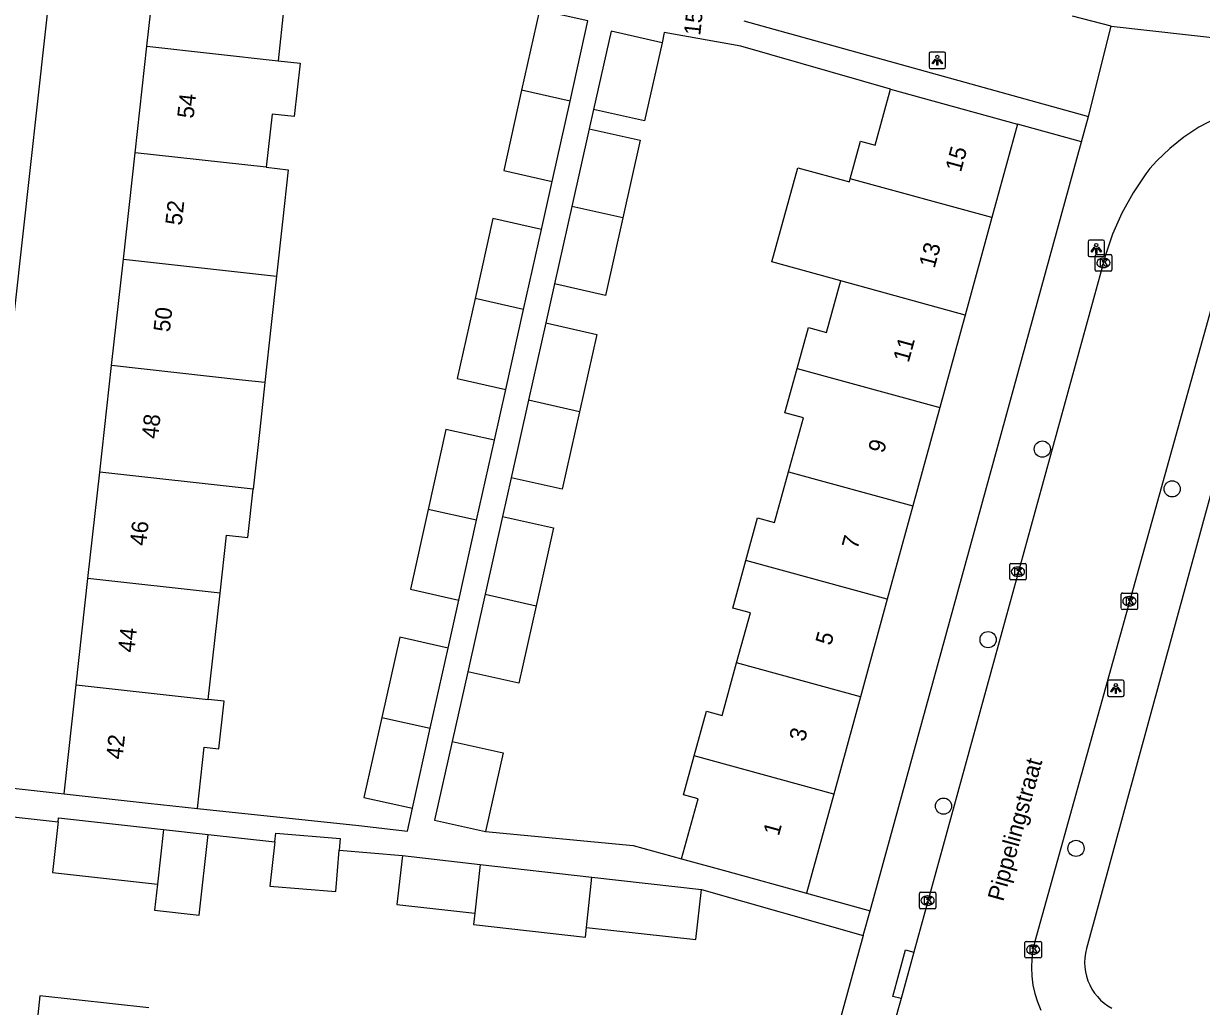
# Model space of a CAD drawing. Extents: x 162026 to 163499, y 387297 to 388169.
# Drawn here: x 162312.4 to 162383.6, y 387852 to 387911.4 of the extents above; entities that cross this region are included whole.
import ezdxf

# ---------------------------------------------------------------- set-up
doc = ezdxf.new("R2010")
doc.units = 0
for name, color, linetype in [('IMGEO_Boom', 7, 'Continuous'), ('IMGEO_Kolk', 7, 'Continuous'), ('IMGEO_Lichtpunt', 7, 'Continuous'), ('IMGEO_Openbare_ruimte_label', 7, 'Continuous'), ('IMGEO_Pand', 7, 'Continuous'), ('IMGEO_Pand_nummerreeks', 7, 'Continuous'), ('IMGEO_Rijbaan_lokaal_open', 7, 'Continuous'), ('IMGEO_Voetpad_open', 7, 'Continuous')]:
    doc.layers.add(name, color=color, linetype=linetype)

msp = doc.modelspace()

# ---------------------------------------------------------------- linework, layer by layer
at = {"layer": 'IMGEO_Boom'}
for centre in [(162373.962, 387885.656), (162381.809, 387883.25), (162370.685, 387874.142), (162367.989, 387864.087), (162375.995, 387861.533)]:
    msp.add_circle(centre, 0.489, dxfattribs=at)
at = {"layer": 'IMGEO_Kolk'}
for p, q in [((162377.153, 387896.475), (162377.153, 387897.327)), ((162377.228, 387897.401), (162378.08, 387897.401)), ((162377.641, 387897.181), (162377.666, 387897.181)), ((162378.154, 387897.327), (162378.154, 387896.475)), ((162378.08, 387896.401), (162377.228, 387896.401)), ((162377.664, 387896.621), (162377.639, 387896.621)), ((162371.989, 387877.823), (162371.989, 387878.675)), ((162372.064, 387878.749), (162372.916, 387878.749)), ((162372.477, 387878.529), (162372.502, 387878.529)), ((162372.99, 387878.675), (162372.99, 387877.823)), ((162372.5, 387877.969), (162372.475, 387877.969)), ((162372.916, 387877.749), (162372.064, 387877.749)), ((162378.722, 387876.035), (162378.722, 387876.887)), ((162378.797, 387876.961), (162379.649, 387876.961)), ((162379.21, 387876.741), (162379.235, 387876.741)), ((162379.723, 387876.887), (162379.723, 387876.035)), ((162379.649, 387875.961), (162378.797, 387875.961)), ((162379.233, 387876.181), (162379.208, 387876.181)), ((162366.53, 387857.956), (162366.53, 387858.808)), ((162366.605, 387858.882), (162367.457, 387858.882)), ((162367.018, 387858.662), (162367.043, 387858.662)), ((162367.531, 387858.808), (162367.531, 387857.956)), ((162367.457, 387857.882), (162366.605, 387857.882)), ((162367.041, 387858.102), (162367.016, 387858.102)), ((162372.904, 387854.99), (162372.904, 387855.842)), ((162372.979, 387855.916), (162373.831, 387855.916)), ((162373.905, 387855.842), (162373.905, 387854.99)), ((162373.415, 387855.136), (162373.39, 387855.136)), ((162373.392, 387855.696), (162373.417, 387855.696)), ((162373.831, 387854.916), (162372.979, 387854.916))]:
    msp.add_line(p, q, dxfattribs=at)
for points in [[(162377.153, 387896.475), (162377.153, 387897.327)], [(162377.228, 387897.401), (162378.08, 387897.401)], [(162377.474, 387897.101), (162377.597, 387897.101), (162377.597, 387896.95), (162377.727, 387897.101), (162377.891, 387897.101), (162377.745, 387896.95), (162377.898, 387896.701), (162377.746, 387896.701), (162377.661, 387896.865), (162377.597, 387896.798), (162377.597, 387896.701), (162377.474, 387896.701), (162377.474, 387897.101)], [(162378.154, 387897.327), (162378.154, 387896.475)], [(162378.08, 387896.401), (162377.228, 387896.401)], [(162371.989, 387877.823), (162371.989, 387878.675)], [(162372.064, 387878.749), (162372.916, 387878.749)], [(162372.99, 387878.675), (162372.99, 387877.823)], [(162372.31, 387878.449), (162372.433, 387878.449), (162372.433, 387878.298), (162372.563, 387878.449), (162372.727, 387878.449), (162372.581, 387878.298), (162372.734, 387878.049), (162372.582, 387878.049), (162372.497, 387878.213), (162372.433, 387878.146), (162372.433, 387878.049), (162372.31, 387878.049), (162372.31, 387878.449)], [(162372.916, 387877.749), (162372.064, 387877.749)], [(162378.722, 387876.035), (162378.722, 387876.887)], [(162378.797, 387876.961), (162379.649, 387876.961)], [(162379.043, 387876.661), (162379.166, 387876.661), (162379.166, 387876.51), (162379.296, 387876.661), (162379.46, 387876.661), (162379.314, 387876.51), (162379.467, 387876.261), (162379.315, 387876.261), (162379.23, 387876.425), (162379.166, 387876.358), (162379.166, 387876.261), (162379.043, 387876.261), (162379.043, 387876.661)], [(162379.723, 387876.887), (162379.723, 387876.035)], [(162379.649, 387875.961), (162378.797, 387875.961)], [(162366.53, 387857.956), (162366.53, 387858.808)], [(162366.605, 387858.882), (162367.457, 387858.882)], [(162366.851, 387858.582), (162366.974, 387858.582), (162366.974, 387858.431), (162367.104, 387858.582), (162367.268, 387858.582), (162367.122, 387858.431), (162367.275, 387858.182), (162367.123, 387858.182), (162367.038, 387858.346), (162366.974, 387858.279), (162366.974, 387858.182), (162366.851, 387858.182), (162366.851, 387858.582)], [(162367.531, 387858.808), (162367.531, 387857.956)], [(162367.457, 387857.882), (162366.605, 387857.882)], [(162372.904, 387854.99), (162372.904, 387855.842)], [(162372.979, 387855.916), (162373.831, 387855.916)], [(162373.905, 387855.842), (162373.905, 387854.99)], [(162373.225, 387855.616), (162373.348, 387855.616), (162373.348, 387855.465), (162373.478, 387855.616), (162373.642, 387855.616), (162373.496, 387855.465), (162373.649, 387855.216), (162373.497, 387855.216), (162373.412, 387855.38), (162373.348, 387855.313), (162373.348, 387855.216), (162373.225, 387855.216), (162373.225, 387855.616)], [(162373.831, 387854.916), (162372.979, 387854.916)]]:
    msp.add_lwpolyline(points, dxfattribs=at)
for centre, start, end in [((162377.23, 387897.325), 91.55205, 178.44795), ((162377.23, 387897.325), 91.55205, 178.44795), ((162378.078, 387897.325), 1.55205, 88.44795), ((162378.078, 387897.325), 1.55205, 88.44795), ((162377.23, 387896.477), 181.55205, 268.44795), ((162377.23, 387896.477), 181.55205, 268.44795), ((162378.078, 387896.477), 271.55205, 358.44795), ((162378.078, 387896.477), 271.55205, 358.44795), ((162372.066, 387878.673), 91.55205, 178.44795), ((162372.066, 387878.673), 91.55205, 178.44795), ((162372.914, 387878.673), 1.55205, 88.44795), ((162372.914, 387878.673), 1.55205, 88.44795), ((162372.066, 387877.825), 181.55205, 268.44795), ((162372.066, 387877.825), 181.55205, 268.44795), ((162372.914, 387877.825), 271.55205, 358.44795), ((162372.914, 387877.825), 271.55205, 358.44795), ((162378.799, 387876.885), 91.55205, 178.44795), ((162378.799, 387876.885), 91.55205, 178.44795), ((162379.647, 387876.885), 1.55205, 88.44795), ((162379.647, 387876.885), 1.55205, 88.44795), ((162378.799, 387876.037), 181.55205, 268.44795), ((162378.799, 387876.037), 181.55205, 268.44795), ((162379.647, 387876.037), 271.55205, 358.44795), ((162379.647, 387876.037), 271.55205, 358.44795), ((162366.607, 387858.806), 91.55205, 178.44795), ((162366.607, 387858.806), 91.55205, 178.44795), ((162367.455, 387858.806), 1.55205, 88.44795), ((162367.455, 387858.806), 1.55205, 88.44795), ((162366.607, 387857.958), 181.55205, 268.44795), ((162366.607, 387857.958), 181.55205, 268.44795), ((162367.455, 387857.958), 271.55205, 358.44795), ((162367.455, 387857.958), 271.55205, 358.44795), ((162372.981, 387855.84), 91.55205, 178.44795), ((162372.981, 387855.84), 91.55205, 178.44795), ((162373.829, 387855.84), 1.55205, 88.44795), ((162373.829, 387855.84), 1.55205, 88.44795), ((162372.981, 387854.992), 181.55205, 268.44795), ((162372.981, 387854.992), 181.55205, 268.44795), ((162373.829, 387854.992), 271.55205, 358.44795), ((162373.829, 387854.992), 271.55205, 358.44795)]:
    msp.add_arc(centre, 0.0765, start, end, dxfattribs=at)
for centre, major_axis, ratio, start_param, end_param in [((162377.64, 387896.901), (-0.387, 0.002), 0.722429, 4.712389, 7.853982), ((162377.665, 387896.901), (-0.39, 0.002), 0.717154, 1.570796, 4.712389), ((162372.476, 387878.249), (-0.387, 0.002), 0.722429, 4.712389, 7.853982), ((162372.501, 387878.249), (-0.39, 0.002), 0.717154, 1.570796, 4.712389), ((162379.209, 387876.461), (-0.387, 0.002), 0.722429, 4.712389, 7.853982), ((162379.234, 387876.461), (-0.39, 0.002), 0.717154, 1.570796, 4.712389), ((162367.017, 387858.382), (-0.387, 0.002), 0.722429, 4.712389, 7.853982), ((162367.042, 387858.382), (-0.39, 0.002), 0.717154, 1.570796, 4.712389), ((162373.391, 387855.416), (-0.387, 0.002), 0.722429, 4.712389, 7.853982), ((162373.416, 387855.416), (-0.39, 0.002), 0.717154, 1.570796, 4.712389)]:
    msp.add_ellipse(centre, major_axis=major_axis, ratio=ratio, start_param=start_param, end_param=end_param, dxfattribs=at)
at = {"layer": 'IMGEO_Lichtpunt'}
for p, q in [((162367.119, 387909.548), (162367.119, 387908.741)), ((162367.119, 387909.548), (162367.119, 387908.741)), ((162368.021, 387909.643), (162367.213, 387909.643)), ((162368.021, 387909.643), (162367.213, 387909.643)), ((162368.115, 387908.741), (162368.115, 387909.548)), ((162368.115, 387908.741), (162368.115, 387909.548)), ((162367.213, 387908.647), (162368.021, 387908.647)), ((162367.213, 387908.647), (162368.021, 387908.647)), ((162376.725, 387898.182), (162376.725, 387897.375)), ((162376.725, 387898.182), (162376.725, 387897.375)), ((162377.627, 387898.277), (162376.819, 387898.277)), ((162377.627, 387898.277), (162376.819, 387898.277)), ((162377.721, 387897.375), (162377.721, 387898.182)), ((162377.721, 387897.375), (162377.721, 387898.182)), ((162376.819, 387897.281), (162377.627, 387897.281)), ((162376.819, 387897.281), (162377.627, 387897.281)), ((162377.905, 387871.603), (162377.905, 387870.796)), ((162377.905, 387871.603), (162377.905, 387870.796)), ((162378.807, 387871.698), (162377.999, 387871.698)), ((162378.807, 387871.698), (162377.999, 387871.698)), ((162378.901, 387870.796), (162378.901, 387871.603)), ((162378.901, 387870.796), (162378.901, 387871.603)), ((162377.999, 387870.702), (162378.807, 387870.702)), ((162377.999, 387870.702), (162378.807, 387870.702))]:
    msp.add_line(p, q, dxfattribs=at)
for points in [[(162367.493, 387909.212), (162367.532, 387909.184), (162367.344, 387908.922), (162367.306, 387908.949), (162367.493, 387909.212)], [(162367.595, 387909.164), (162367.642, 387909.164), (162367.642, 387908.842), (162367.595, 387908.842), (162367.595, 387909.164)], [(162367.705, 387909.184), (162367.743, 387909.211), (162367.93, 387908.949), (162367.891, 387908.921), (162367.705, 387909.184)], [(162377.099, 387897.846), (162377.138, 387897.818), (162376.95, 387897.556), (162376.912, 387897.583), (162377.099, 387897.846)], [(162377.201, 387897.798), (162377.248, 387897.798), (162377.248, 387897.476), (162377.201, 387897.476), (162377.201, 387897.798)], [(162377.311, 387897.818), (162377.349, 387897.845), (162377.536, 387897.583), (162377.497, 387897.555), (162377.311, 387897.818)], [(162378.279, 387871.267), (162378.318, 387871.239), (162378.13, 387870.977), (162378.092, 387871.004), (162378.279, 387871.267)], [(162378.381, 387871.219), (162378.428, 387871.219), (162378.428, 387870.897), (162378.381, 387870.897), (162378.381, 387871.219)], [(162378.491, 387871.239), (162378.529, 387871.266), (162378.716, 387871.004), (162378.677, 387870.976), (162378.491, 387871.239)]]:
    msp.add_lwpolyline(points, dxfattribs=at)
for centre in [(162367.618, 387909.346), (162377.224, 387897.98), (162378.404, 387871.401)]:
    msp.add_circle(centre, 0.0994, dxfattribs=at)
for centre, start, end in [((162367.213, 387909.548), 90, 180), ((162367.213, 387909.548), 90, 180), ((162368.021, 387909.548), 0, 90), ((162368.021, 387909.548), 0, 90), ((162367.213, 387908.741), 180, 270), ((162367.213, 387908.741), 180, 270), ((162368.021, 387908.741), 270, 0), ((162368.021, 387908.741), 270, 360), ((162376.819, 387898.182), 90, 180), ((162376.819, 387898.182), 90, 180), ((162377.627, 387898.182), 0, 90), ((162377.627, 387898.182), 0, 90), ((162376.819, 387897.375), 180, 270), ((162376.819, 387897.375), 180, 270), ((162377.627, 387897.375), 270, 0), ((162377.627, 387897.375), 270, 360), ((162377.999, 387871.603), 90, 180), ((162377.999, 387871.603), 90, 180), ((162378.807, 387871.603), 0, 90), ((162378.807, 387871.603), 0, 90), ((162377.999, 387870.796), 180, 270), ((162377.999, 387870.796), 180, 270), ((162378.807, 387870.796), 270, 0), ((162378.807, 387870.796), 270, 360)]:
    msp.add_arc(centre, 0.0946, start, end, dxfattribs=at)
at = {"layer": 'IMGEO_Pand'}
for points in [[(162319.856, 387909.991), (162320.57, 387916.422)], [(162329.812, 387915.352), (162329.461, 387912.18), (162328.136, 387912.328), (162327.779, 387909.112)], [(162346.5, 387911.524), (162343.572, 387912.176), (162342.493, 387907.335)], [(162345.421, 387906.683), (162346.5, 387911.524)], [(162350.983, 387910.206), (162347.9, 387910.896), (162346.842, 387906.172)], [(162319.142, 387903.561), (162319.856, 387909.991)], [(162319.856, 387909.991), (162327.779, 387909.112)], [(162350.983, 387910.206), (162349.926, 387905.482), (162346.842, 387906.172)], [(162327.779, 387909.112), (162329.105, 387908.965), (162328.748, 387905.75), (162327.422, 387905.897), (162327.065, 387902.682)], [(162342.493, 387907.335), (162341.411, 387902.481), (162344.339, 387901.828)], [(162345.421, 387906.683), (162342.493, 387907.335)], [(162362.357, 387901.984), (162362.983, 387904.262), (162363.86, 387904.021), (162364.786, 387907.396)], [(162364.786, 387907.396), (162372.461, 387905.289)], [(162344.339, 387901.828), (162345.421, 387906.683)], [(162346.58, 387904.999), (162345.532, 387900.319)], [(162346.58, 387904.999), (162349.663, 387904.309), (162348.616, 387899.628)], [(162372.461, 387905.289), (162370.91, 387899.638)], [(162318.428, 387897.13), (162319.142, 387903.561)], [(162327.065, 387902.682), (162319.142, 387903.561)], [(162327.065, 387902.682), (162328.392, 387902.535), (162328.043, 387899.381), (162327.68, 387896.104)], [(162361.781, 387895.815), (162357.616, 387896.958), (162359.181, 387902.656), (162362.306, 387901.798), (162362.357, 387901.984)], [(162370.91, 387899.638), (162362.357, 387901.984)], [(162345.532, 387900.319), (162344.483, 387895.634)], [(162348.616, 387899.628), (162345.532, 387900.319)], [(162343.692, 387898.924), (162340.763, 387899.576), (162339.687, 387894.745)], [(162348.616, 387899.628), (162347.567, 387894.944), (162344.483, 387895.634)], [(162370.91, 387899.638), (162369.296, 387893.753)], [(162342.615, 387894.092), (162343.692, 387898.924)], [(162317.715, 387890.7), (162318.428, 387897.13)], [(162318.428, 387897.13), (162327.68, 387896.104)], [(162327.68, 387896.104), (162327.356, 387893.185), (162326.981, 387889.672)], [(162359.147, 387890.524), (162359.828, 387893.001), (162360.924, 387892.699), (162361.728, 387895.622), (162361.781, 387895.815)], [(162369.296, 387893.753), (162361.781, 387895.815)], [(162339.687, 387894.745), (162338.61, 387889.913), (162341.538, 387889.26)], [(162342.615, 387894.092), (162339.687, 387894.745)], [(162341.538, 387889.26), (162342.615, 387894.092)], [(162369.296, 387893.753), (162367.762, 387888.161)], [(162343.956, 387893.278), (162342.909, 387888.601)], [(162343.956, 387893.278), (162347.04, 387892.588), (162345.993, 387887.911)], [(162317.001, 387884.269), (162317.715, 387890.7)], [(162326.981, 387889.672), (162325.601, 387889.825), (162317.715, 387890.7)], [(162358.631, 387884.287), (162359.525, 387887.538), (162358.41, 387887.845), (162359.147, 387890.524)], [(162359.147, 387890.524), (162367.762, 387888.161)], [(162326.981, 387889.672), (162326.678, 387886.836), (162326.279, 387883.24)], [(162342.909, 387888.601), (162341.861, 387883.917)], [(162345.993, 387887.911), (162342.909, 387888.601)], [(162345.993, 387887.911), (162344.944, 387883.227), (162341.861, 387883.917)], [(162367.762, 387888.161), (162366.134, 387882.228)], [(162340.854, 387886.194), (162337.926, 387886.847), (162336.849, 387882.015)], [(162339.777, 387881.363), (162340.854, 387886.194)], [(162316.287, 387877.839), (162317.001, 387884.269)], [(162326.279, 387883.24), (162317.001, 387884.269)], [(162356.048, 387878.929), (162356.756, 387881.503), (162357.787, 387881.22), (162358.631, 387884.287)], [(162358.631, 387884.287), (162366.134, 387882.228)], [(162324.277, 387876.953), (162324.665, 387880.449), (162325.953, 387880.306), (162326.279, 387883.24)], [(162366.134, 387882.228), (162364.586, 387876.586)], [(162336.849, 387882.015), (162335.774, 387877.19), (162338.702, 387876.537)], [(162339.777, 387881.363), (162336.849, 387882.015)], [(162338.702, 387876.537), (162339.777, 387881.363)], [(162341.338, 387881.581), (162340.286, 387876.884)], [(162341.338, 387881.581), (162344.422, 387880.891), (162343.37, 387876.193)], [(162355.487, 387872.733), (162356.32, 387875.762), (162355.257, 387876.054), (162356.048, 387878.929)], [(162364.586, 387876.586), (162356.048, 387878.929)], [(162315.573, 387871.408), (162316.287, 387877.839)], [(162324.277, 387876.953), (162316.287, 387877.839)], [(162323.563, 387870.522), (162323.96, 387874.098), (162324.277, 387876.953)], [(162340.286, 387876.884), (162339.238, 387872.199)], [(162340.286, 387876.884), (162343.37, 387876.193)], [(162364.586, 387876.586), (162362.966, 387870.681)], [(162343.37, 387876.193), (162342.322, 387871.509), (162339.238, 387872.199)], [(162338.055, 387873.637), (162335.127, 387874.289), (162334.048, 387869.448)], [(162336.976, 387868.796), (162338.055, 387873.637)], [(162352.93, 387867.127), (162353.673, 387869.826), (162354.616, 387869.567), (162355.487, 387872.733)], [(162362.966, 387870.681), (162355.487, 387872.733)], [(162314.843, 387864.833), (162315.573, 387871.408)], [(162315.573, 387871.408), (162323.563, 387870.522)], [(162362.966, 387870.681), (162361.356, 387864.815)], [(162322.905, 387863.938), (162323.317, 387867.641), (162324.194, 387867.544), (162324.513, 387870.417), (162323.563, 387870.522)], [(162334.048, 387869.448), (162332.969, 387864.606), (162335.897, 387863.953)], [(162334.048, 387869.448), (162336.976, 387868.796)], [(162335.897, 387863.953), (162336.976, 387868.796)], [(162338.297, 387867.996), (162337.233, 387863.244), (162340.317, 387862.554)], [(162338.297, 387867.996), (162341.381, 387867.306), (162340.317, 387862.554)], [(162352.16, 387860.899), (162353.156, 387864.523), (162352.279, 387864.765), (162352.93, 387867.127)], [(162361.356, 387864.815), (162352.93, 387867.127)], [(162314.843, 387864.833), (162319.929, 387864.268), (162322.905, 387863.938)], [(162361.356, 387864.815), (162359.712, 387858.822)], [(162314.493, 387863.145), (162314.473, 387862.966), (162314.154, 387860.073), (162320.493, 387859.372)], [(162314.493, 387863.145), (162314.519, 387863.376), (162320.858, 387862.674)], [(162320.493, 387859.372), (162320.318, 387857.792), (162323.014, 387857.494), (162323.554, 387862.376)], [(162320.858, 387862.674), (162320.493, 387859.372)], [(162320.858, 387862.674), (162323.554, 387862.376)], [(162327.579, 387861.931), (162327.636, 387862.448), (162331.526, 387862.132), (162331.469, 387861.432)], [(162327.579, 387861.931), (162327.283, 387859.256), (162331.267, 387858.933), (162331.469, 387861.432)], [(162335.295, 387861.097), (162334.962, 387858.147), (162339.666, 387857.615)], [(162335.295, 387861.097), (162340, 387860.564)], [(162352.16, 387860.899), (162354.892, 387860.148), (162359.712, 387858.822)], [(162340, 387860.564), (162339.666, 387857.615)], [(162340, 387860.564), (162346.737, 387859.801)], [(162346.421, 387856.761), (162346.737, 387859.801)], [(162346.737, 387859.801), (162353.359, 387859.051)], [(162346.421, 387856.761), (162353.025, 387856.03), (162353.359, 387859.051)], [(162339.666, 387857.615), (162339.59, 387856.943), (162346.36, 387856.177), (162346.421, 387856.761)], [(162319.961, 387851.902), (162313.38, 387852.629), (162313.252, 387851.47), (162312.238, 387842.298), (162318.819, 387841.57)]]:
    msp.add_lwpolyline(points, dxfattribs=at)
at = {"layer": 'IMGEO_Rijbaan_lokaal_open'}
for points in [[(162355.919, 387911.519), (162376.751, 387905.75)], [(162378.114, 387911.206), (162375.788, 387911.805)], [(162376.751, 387905.75), (162378.114, 387911.206)], [(162413.007, 387904.243), (162390.676, 387906.786), (162389.589, 387906.828), (162388.503, 387906.772), (162387.427, 387906.62), (162386.368, 387906.372), (162385.377, 387906.046), (162384.377, 387905.617), (162383.42, 387905.1), (162382.513, 387904.5), (162381.663, 387903.821), (162380.877, 387903.069), (162380.456, 387902.605), (162380.22, 387902.293), (162379.442, 387901.135), (162378.771, 387899.911), (162378.211, 387898.633), (162377.769, 387897.31), (162377.721, 387897.14), (162366.207, 387855.262)], [(162384.168, 387894.147), (162373.517, 387855.908), (162373.398, 387855.391), (162373.326, 387854.865), (162373.301, 387854.335), (162373.324, 387853.805), (162373.394, 387853.279), (162373.511, 387852.762), (162373.673, 387852.257), (162373.88, 387851.768)], [(162366.207, 387855.262), (162365.437, 387852.458)], [(162365.437, 387852.458), (162358.905, 387829.486), (162356.187, 387819.834)]]:
    msp.add_lwpolyline(points, dxfattribs=at)
at = {"layer": 'IMGEO_Voetpad_open'}
for points in [[(162317.966, 387949.406), (162317.334, 387943.671), (162308.672, 387865.517)], [(162364.786, 387907.396), (162355.735, 387909.999), (162351.114, 387910.828), (162350.983, 387910.206)], [(162378.114, 387911.206), (162413.36, 387907.265)], [(162346.842, 387906.172), (162346.58, 387904.999)], [(162376.332, 387904.226), (162376.751, 387905.75)], [(162376.332, 387904.226), (162372.461, 387905.289)], [(162363.55, 387857.766), (162376.332, 387904.226)], [(162343.692, 387898.924), (162344.339, 387901.828)], [(162344.483, 387895.634), (162343.956, 387893.278)], [(162387.217, 387894.235), (162376.626, 387855.48), (162376.564, 387855.205), (162376.527, 387854.925), (162376.515, 387854.643), (162376.528, 387854.362), (162376.566, 387854.082), (162376.629, 387853.807), (162376.716, 387853.539), (162376.827, 387853.28), (162376.961, 387853.031), (162377.116, 387852.796), (162377.292, 387852.575), (162377.487, 387852.371), (162377.699, 387852.185), (162377.927, 387852.019), (162378.169, 387851.874)], [(162340.854, 387886.194), (162341.538, 387889.26)], [(162341.861, 387883.917), (162341.338, 387881.581)], [(162338.055, 387873.637), (162338.702, 387876.537)], [(162339.238, 387872.199), (162338.297, 387867.996)], [(162308.672, 387865.517), (162314.843, 387864.833)], [(162308.483, 387863.811), (162314.493, 387863.145)], [(162322.905, 387863.938), (162332.654, 387862.91), (162335.59, 387862.578), (162335.897, 387863.953)], [(162323.554, 387862.376), (162327.579, 387861.931)], [(162340.317, 387862.554), (162349.227, 387861.704), (162352.16, 387860.899)], [(162331.469, 387861.432), (162335.295, 387861.097)], [(162353.359, 387859.051), (162363.137, 387856.266)], [(162359.712, 387858.822), (162363.55, 387857.766)], [(162363.137, 387856.266), (162363.55, 387857.766)], [(162363.137, 387856.266), (162356.323, 387831.497), (162355.765, 387829.226)], [(162365.437, 387852.458), (162364.924, 387852.592), (162365.694, 387855.396), (162366.207, 387855.262)]]:
    msp.add_lwpolyline(points, dxfattribs=at)

# ---------------------------------------------------------------- texts
at = {"layer": 'IMGEO_Openbare_ruimte_label'}
msp.add_text('Pippelingstraat', height=1, rotation=74.44828, dxfattribs=at).set_placement((162371.6, 387858.28))
at = {"layer": 'IMGEO_Pand_nummerreeks'}
for s, rotation, p in [('15/G01', 83.73867, (162353.286, 387910.611)), ('54', 83.66535, (162322.669, 387905.596)), ('15', 74.65749, (162369.04, 387902.342)), ('52', 83.66535, (162321.952, 387899.139)), ('13', 74.6564, (162367.446, 387896.534)), ('50', 83.66535, (162321.236, 387892.692)), ('11', 74.6564, (162365.882, 387890.835)), ('48', 83.66535, (162320.52, 387886.239)), ('9', 74.65749, (162364.38, 387885.361)), ('46', 83.66535, (162319.803, 387879.783)), ('7', 74.65749, (162362.786, 387879.553)), ('44', 83.6633, (162319.087, 387873.33)), ('5', 74.65749, (162361.192, 387873.744)), ('3', 74.65749, (162359.599, 387867.936)), ('42', 83.6633, (162318.37, 387866.874)), ('1', 74.65749, (162358.035, 387862.237))]:
    msp.add_text(s, height=1, rotation=rotation, dxfattribs=at).set_placement(p)

doc.saveas('drawing.dxf')
